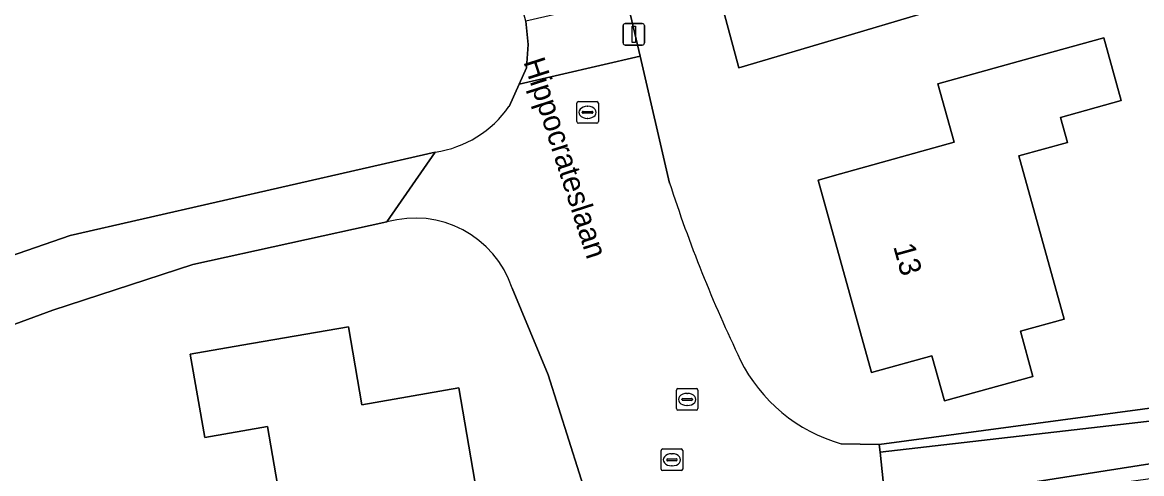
# Model space of a CAD drawing. Extents: x 162156 to 163172, y 378995 to 380779.
# Drawn here: x 162712.5 to 162764.3, y 380088.4 to 380109.3 of the extents above; entities that cross this region are included whole.
import ezdxf

# ---------------------------------------------------------------- set-up
doc = ezdxf.new("R2010")
doc.units = 0
for name, color, linetype in [('IMGEO_Brandkraan', 7, 'Continuous'), ('IMGEO_Erf', 7, 'Continuous'), ('IMGEO_Groenvoorziening', 7, 'Continuous'), ('IMGEO_Haag', 7, 'Continuous'), ('IMGEO_Kolk', 7, 'Continuous'), ('IMGEO_Lichtmast', 7, 'Continuous'), ('IMGEO_Naaldbos', 7, 'Continuous'), ('IMGEO_Openbare_ruimte_label', 7, 'Continuous'), ('IMGEO_Pand', 7, 'Continuous'), ('IMGEO_Pand_nummerreeks', 7, 'Continuous'), ('IMGEO_Rijbaan_lokaal_open', 7, 'Continuous'), ('IMGEO_Voetpad_halfverhard', 7, 'Continuous')]:
    doc.layers.add(name, color=color, linetype=linetype)

msp = doc.modelspace()

# ---------------------------------------------------------------- linework, layer by layer
at = {"layer": 'IMGEO_Brandkraan'}
for p, q in [((162742.8, 380091.428), (162742.8, 380092.28)), ((162742.875, 380092.354), (162743.727, 380092.354)), ((162743.801, 380092.28), (162743.801, 380091.428)), ((162743.059, 380091.848), (162743.059, 380091.86)), ((162743.497, 380091.811), (162743.099, 380091.811)), ((162743.102, 380091.897), (162743.5, 380091.897)), ((162743.288, 380092.134), (162743.313, 380092.134)), ((162743.543, 380091.86), (162743.543, 380091.848)), ((162743.727, 380091.354), (162742.875, 380091.354)), ((162743.311, 380091.574), (162743.286, 380091.574))]:
    msp.add_line(p, q, dxfattribs=at)
for points in [[(162742.8, 380091.428), (162742.8, 380092.28)], [(162742.875, 380092.354), (162743.727, 380092.354)], [(162743.801, 380092.28), (162743.801, 380091.428)], [(162743.727, 380091.354), (162742.875, 380091.354)]]:
    msp.add_lwpolyline(points, dxfattribs=at)
for centre, radius, start, end in [((162742.877, 380092.278), 0.0765, 91.552, 178.448), ((162742.877, 380092.278), 0.0765, 91.552, 178.448), ((162743.725, 380092.278), 0.0765, 1.552, 88.448), ((162743.725, 380092.278), 0.0765, 1.552, 88.448), ((162743.099, 380091.857), 0.0403, 85.8775, 175.7526), ((162743.096, 380091.847), 0.0366, 178.938, 274.7102), ((162743.5, 380091.854), 0.043, 264.8664, 352.4533), ((162743.504, 380091.859), 0.0386, 1.7309, 96.639), ((162742.877, 380091.43), 0.0765, 181.552, 268.448), ((162742.877, 380091.43), 0.0765, 181.552, 268.448), ((162743.725, 380091.43), 0.0765, 271.552, 358.448), ((162743.725, 380091.43), 0.0765, 271.552, 358.448)]:
    msp.add_arc(centre, radius, start, end, dxfattribs=at)
for centre, major_axis, ratio, start_param, end_param in [((162743.287, 380091.854), (-0.387, 0.002), 0.722429, 4.712389, 7.853982), ((162743.312, 380091.854), (-0.39, 0.002), 0.717154, 1.570796, 4.712389)]:
    msp.add_ellipse(centre, major_axis=major_axis, ratio=ratio, start_param=start_param, end_param=end_param, dxfattribs=at)
at = {"layer": 'IMGEO_Erf'}
for points in [[(162750.429, 380089.805), (162752.191, 380089.762), (162777.588, 380093.171), (162757.756, 380165.253)], [(162666.225, 380138.522), (162664.994, 380136.169), (162665.017, 380131.245), (162667.515, 380116.396), (162669.104, 380111.454), (162670.935, 380107.393), (162674.348, 380097.308), (162688.685, 380094.714), (162691.981, 380094.399), (162693.865, 380094.119), (162696.25, 380093.992), (162698.635, 380094.115), (162700.994, 380094.486), (162702.891, 380094.89), (162704.592, 380095.451), (162706.226, 380096.187), (162709.98, 380097.788), (162714.749, 380099.439), (162731.647, 380103.299)], [(162736.289, 380124.676), (162737.884, 380120.234), (162739.273, 380115.723), (162740.499, 380110.432), (162741.124, 380107.734), (162742.484, 380101.867)], [(162735.058, 380105.41), (162735.522, 380106.436), (162735.864, 380107.191), (162735.945, 380108.272), (162735.832, 380109.35), (162733.255, 380118.91)], [(162729.408, 380100.063), (162720.422, 380098.094), (162713.945, 380095.981), (162707.667, 380093.669), (162709.547, 380072.093), (162684.738, 380059.133), (162663.781, 380052.371)], [(162745.934, 380050.387), (162745.646, 380053.135), (162745.356, 380055.89), (162744.874, 380060.475), (162743.982, 380065.693), (162742.961, 380072.097), (162741.01, 380079.537), (162740.552, 380081.997), (162739.257, 380085.438), (162736.865, 380092.998), (162735.21, 380096.999)]]:
    msp.add_lwpolyline(points, dxfattribs=at)
for points in [[(162750.337, 380117.735), (162749.298, 380121.599), (162748.98, 380122.782), (162759.669, 380125.657), (162760.937, 380120.943), (162760.362, 380120.008), (162757.429, 380119.22), (162758.499, 380115.24), (162756.636, 380114.758), (162757.737, 380110.668), (162754.014, 380109.666), (162750.486, 380108.619), (162745.692, 380107.196), (162743.362, 380115.859), (162745.415, 380116.411)], [(162750.395, 380102.291), (162755.656, 380103.75), (162754.904, 380106.46), (162759.723, 380107.797), (162762.574, 380108.588), (162763.38, 380105.68), (162760.582, 380104.904), (162760.905, 380103.743), (162758.652, 380103.118), (162760.745, 380095.572), (162758.719, 380095.01), (162759.298, 380092.922), (162755.207, 380091.787), (162754.628, 380093.875), (162751.832, 380093.099), (162749.361, 380102.004)], [(162725.876, 380079.071), (162723.887, 380090.596), (162720.98, 380090.094), (162720.313, 380093.955), (162722.702, 380094.367), (162727.629, 380095.218), (162728.252, 380091.611), (162732.731, 380092.384), (162734.764, 380080.605), (162729.837, 380079.755)]]:
    msp.add_lwpolyline(points, close=True, dxfattribs=at)
for centre, radius, start, end in [((162730.946, 380108.243), 4.993, 278.0679, 325.4372), ((162805.535, 380122.376), 66.303, 198.01828, 205.63768), ((162730.713, 380095.508), 4.738, 18.3384, 105.9851), ((162752.434, 380096.964), 7.434, 206.1457, 254.3567)]:
    msp.add_arc(centre, radius, start, end, dxfattribs=at)
at = {"layer": 'IMGEO_Groenvoorziening'}
for points in [[(162777.811, 380092.358), (162777.588, 380093.171), (162752.191, 380089.762), (162752.226, 380089.421)], [(162777.292, 380089.936), (162778.432, 380090.094), (162778.296, 380090.589), (162773.022, 380089.753), (162766.283, 380089.121), (162759.488, 380088.056), (162758.624, 380087.614), (162753.526, 380087.112), (162753.541, 380086.852), (162760.842, 380087.653)]]:
    msp.add_lwpolyline(points, close=True, dxfattribs=at)
at = {"layer": 'IMGEO_Haag'}
msp.add_lwpolyline([(162777.811, 380092.358), (162777.588, 380093.171), (162752.191, 380089.762), (162752.226, 380089.421)], close=True, dxfattribs=at)
at = {"layer": 'IMGEO_Kolk'}
for p, q in [((162738.266, 380105.636), (162739.118, 380105.636)), ((162738.191, 380104.71), (162738.191, 380105.562)), ((162738.45, 380105.13), (162738.45, 380105.142)), ((162738.493, 380105.179), (162738.891, 380105.179)), ((162738.679, 380105.416), (162738.704, 380105.416)), ((162738.934, 380105.142), (162738.934, 380105.13)), ((162739.192, 380105.562), (162739.192, 380104.71)), ((162739.118, 380104.636), (162738.266, 380104.636)), ((162738.888, 380105.093), (162738.49, 380105.093)), ((162738.702, 380104.856), (162738.677, 380104.856)), ((162742.095, 380088.635), (162742.095, 380089.487)), ((162742.17, 380089.561), (162743.022, 380089.561)), ((162742.354, 380089.055), (162742.354, 380089.067)), ((162742.397, 380089.104), (162742.795, 380089.104)), ((162742.583, 380089.341), (162742.608, 380089.341)), ((162742.838, 380089.067), (162742.838, 380089.055)), ((162743.096, 380089.487), (162743.096, 380088.635)), ((162743.022, 380088.561), (162742.17, 380088.561)), ((162742.792, 380089.018), (162742.394, 380089.018)), ((162742.606, 380088.781), (162742.581, 380088.781))]:
    msp.add_line(p, q, dxfattribs=at)
for points in [[(162738.266, 380105.636), (162739.118, 380105.636)], [(162738.191, 380104.71), (162738.191, 380105.562)], [(162739.192, 380105.562), (162739.192, 380104.71)], [(162739.118, 380104.636), (162738.266, 380104.636)], [(162742.095, 380088.635), (162742.095, 380089.487)], [(162742.17, 380089.561), (162743.022, 380089.561)], [(162743.096, 380089.487), (162743.096, 380088.635)], [(162743.022, 380088.561), (162742.17, 380088.561)]]:
    msp.add_lwpolyline(points, dxfattribs=at)
for centre, radius, start, end in [((162738.268, 380105.56), 0.0765, 91.552, 178.448), ((162738.268, 380105.56), 0.0765, 91.552, 178.448), ((162739.116, 380105.56), 0.0765, 1.552, 88.448), ((162739.116, 380105.56), 0.0765, 1.552, 88.448), ((162738.49, 380105.139), 0.0403, 85.8775, 175.7526), ((162738.487, 380105.129), 0.0366, 178.938, 274.7102), ((162738.891, 380105.136), 0.043, 264.8664, 352.4533), ((162738.895, 380105.141), 0.0386, 1.7309, 96.639), ((162738.268, 380104.712), 0.0765, 181.552, 268.448), ((162738.268, 380104.712), 0.0765, 181.552, 268.448), ((162739.116, 380104.712), 0.0765, 271.552, 358.448), ((162739.116, 380104.712), 0.0765, 271.552, 358.448), ((162742.172, 380089.485), 0.0765, 91.552, 178.448), ((162742.172, 380089.485), 0.0765, 91.552, 178.448), ((162742.394, 380089.064), 0.0403, 85.8775, 175.7526), ((162742.391, 380089.054), 0.0366, 178.938, 274.7102), ((162742.795, 380089.061), 0.043, 264.8664, 352.4533), ((162742.799, 380089.066), 0.0386, 1.7309, 96.639), ((162743.02, 380089.485), 0.0765, 1.552, 88.448), ((162743.02, 380089.485), 0.0765, 1.552, 88.448), ((162742.172, 380088.637), 0.0765, 181.552, 268.448), ((162742.172, 380088.637), 0.0765, 181.552, 268.448), ((162743.02, 380088.637), 0.0765, 271.552, 358.448), ((162743.02, 380088.637), 0.0765, 271.552, 358.448)]:
    msp.add_arc(centre, radius, start, end, dxfattribs=at)
for centre, major_axis, ratio, start_param, end_param in [((162738.678, 380105.136), (-0.387, 0.002), 0.722429, 4.712389, 7.853982), ((162738.703, 380105.136), (-0.39, 0.002), 0.717154, 1.570796, 4.712389), ((162742.582, 380089.061), (-0.387, 0.002), 0.722429, 4.712389, 7.853982), ((162742.607, 380089.061), (-0.39, 0.002), 0.717154, 1.570796, 4.712389)]:
    msp.add_ellipse(centre, major_axis=major_axis, ratio=ratio, start_param=start_param, end_param=end_param, dxfattribs=at)
at = {"layer": 'IMGEO_Lichtmast'}
for p, q in [((162740.434, 380109.246), (162741.224, 380109.246)), ((162741.224, 380109.246), (162740.434, 380109.246)), ((162740.334, 380108.346), (162740.334, 380109.146)), ((162740.334, 380109.146), (162740.334, 380108.346)), ((162741.324, 380109.146), (162741.324, 380108.346)), ((162741.324, 380108.346), (162741.324, 380109.146)), ((162741.224, 380108.246), (162740.434, 380108.246)), ((162740.434, 380108.246), (162741.224, 380108.246))]:
    msp.add_line(p, q, dxfattribs=at)
msp.add_lwpolyline([(162740.754, 380109.121), (162740.904, 380109.121), (162740.904, 380108.371), (162740.754, 380108.371), (162740.754, 380109.121)], dxfattribs=at)
for centre, start, end in [((162740.434, 380109.146), 90, 180), ((162740.434, 380109.146), 90, 180), ((162741.224, 380109.146), 0, 90), ((162741.224, 380109.146), 360, 90), ((162740.434, 380108.346), 180, 270), ((162740.434, 380108.346), 180, 270), ((162741.224, 380108.346), 270, 0), ((162741.224, 380108.346), 270, 0)]:
    msp.add_arc(centre, 0.1, start, end, dxfattribs=at)
at = {"layer": 'IMGEO_Naaldbos'}
msp.add_lwpolyline([(162707.667, 380093.669), (162713.945, 380095.981), (162720.422, 380098.094), (162729.408, 380100.063), (162731.647, 380103.299), (162714.749, 380099.439), (162709.98, 380097.788), (162706.226, 380096.187), (162704.592, 380095.451), (162702.891, 380094.89), (162700.994, 380094.486), (162698.635, 380094.115), (162696.25, 380093.992), (162693.865, 380094.119), (162691.981, 380094.399), (162688.685, 380094.714), (162674.348, 380097.308), (162670.935, 380107.393), (162669.104, 380111.454), (162667.515, 380116.396), (162665.017, 380131.245), (162664.994, 380136.169), (162666.225, 380138.522), (162664.523, 380139.522)], dxfattribs=at)
at = {"layer": 'IMGEO_Pand'}
for points in [[(162749.298, 380121.599), (162750.337, 380117.735), (162745.415, 380116.411), (162743.362, 380115.859), (162745.692, 380107.196), (162750.486, 380108.619), (162754.014, 380109.666), (162757.737, 380110.668), (162756.636, 380114.758), (162758.499, 380115.24), (162757.429, 380119.22), (162760.362, 380120.008), (162760.937, 380120.943), (162759.669, 380125.657), (162748.98, 380122.782)], [(162758.652, 380103.118), (162760.905, 380103.743), (162760.582, 380104.904), (162763.38, 380105.68), (162762.574, 380108.588), (162759.723, 380107.797), (162754.904, 380106.46), (162755.656, 380103.75), (162750.395, 380102.291), (162749.361, 380102.004), (162751.832, 380093.099), (162754.628, 380093.875), (162755.207, 380091.787), (162759.298, 380092.922), (162758.719, 380095.01), (162760.745, 380095.572)], [(162729.837, 380079.755), (162734.764, 380080.605), (162732.731, 380092.384), (162728.252, 380091.611), (162727.629, 380095.218), (162722.702, 380094.367), (162720.313, 380093.955), (162720.98, 380090.094), (162723.887, 380090.596), (162725.876, 380079.071)]]:
    msp.add_lwpolyline(points, close=True, dxfattribs=at)
at = {"layer": 'IMGEO_Rijbaan_lokaal_open'}
msp.add_lwpolyline([(162735.522, 380106.436), (162741.124, 380107.734), (162740.499, 380110.432), (162735.832, 380109.35), (162735.945, 380108.272), (162735.864, 380107.191)], close=True, dxfattribs=at)
for points in [[(162742.484, 380101.867), (162741.124, 380107.734), (162735.522, 380106.436), (162735.058, 380105.41)], [(162731.647, 380103.299), (162729.408, 380100.063)], [(162735.21, 380096.999), (162736.865, 380092.998), (162739.257, 380085.438), (162740.552, 380081.997), (162741.01, 380079.537), (162742.961, 380072.097), (162743.982, 380065.693), (162744.874, 380060.475), (162745.356, 380055.89), (162750.303, 380056.357), (162748.634, 380068.952), (162747.58, 380073.972), (162745.151, 380083.912)], [(162746.771, 380085.889), (162752.503, 380086.738), (162752.226, 380089.421), (162752.191, 380089.762), (162750.429, 380089.805)]]:
    msp.add_lwpolyline(points, dxfattribs=at)
for centre, radius, start, end in [((162730.946, 380108.243), 4.993, 278.0679, 325.4372), ((162805.535, 380122.376), 66.303, 198.01828, 205.63768), ((162730.713, 380095.508), 4.738, 18.3384, 105.9851), ((162752.434, 380096.964), 7.434, 206.1457, 254.3567)]:
    msp.add_arc(centre, radius, start, end, dxfattribs=at)
at = {"layer": 'IMGEO_Voetpad_halfverhard'}
msp.add_lwpolyline([(162778.296, 380090.589), (162777.811, 380092.358), (162752.226, 380089.421), (162752.503, 380086.738), (162753.541, 380086.852), (162753.526, 380087.112), (162758.624, 380087.614), (162759.488, 380088.056), (162766.283, 380089.121), (162773.022, 380089.753)], close=True, dxfattribs=at)

# ---------------------------------------------------------------- texts
at = {"layer": 'IMGEO_Openbare_ruimte_label'}
msp.add_text('Hippocrateslaan', height=1, rotation=287.8734, dxfattribs=at).set_placement((162735.717, 380107.481))
at = {"layer": 'IMGEO_Pand_nummerreeks'}
msp.add_text('13', height=1, rotation=285.5098, dxfattribs=at).set_placement((162752.828, 380098.934))

doc.saveas('drawing.dxf')
